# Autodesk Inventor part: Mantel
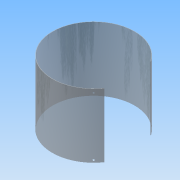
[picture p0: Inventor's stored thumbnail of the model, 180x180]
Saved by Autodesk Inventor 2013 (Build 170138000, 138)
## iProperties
Created: 2012-10
Part Number: Mantel
Material: Glas
Document SubType Name: Blech
Designer: Ente
Density: 2.18 g/cm^3
Mass: 137.687 g
Surface Area: 1275.35 cm^2
Volume: 63.1592 cm^3
Sheet Metal Rule: Standard
Author: Ente
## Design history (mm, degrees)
sketch "Skizze1"
  geometry: L1 (0, -27.3)-(0, 163.8) reference; L2 (-123.9, 0)-(123.9, 0) reference; L3 (88.125, 0)-(87.125, 0); L4 (87.125, 0)-(87.125, 136.5); L5 (87.125, 136.5)-(88.125, 136.5); L6 (88.125, 136.5)-(88.125, 0); 1 further point
  constraints: 8 end point, 2 parallel, 1 horizontal, 1 perpendicular, 1 point on line
  dimensions: "d0" = 1 distance of L4.end L5.end; "d3" = 136.5 distance of L5.end L3.start; "d5" = 174.25 diameter of L4 L1
revolve "Umdrehung1" sketch "Skizze1" stored, may be unused: angle "d4" = 291 deg
workplane "Arbeitsebene4"
  workplane "Arbeitsebene3"
sketch "Skizze3"
  geometry: L1 (0, -98.25)-(0, 96) reference; L2 (-175.221, -68.25)-(175.221, -68.25) reference; 2 further points
  constraints: 1 point on line
  dimensions: "d12" = 5 distance from line of L2 point (0, -63.25)
hole "Bohrung1" sketch "Skizze3" at (0, -63.25) diameter "d13" = 3.4; stored, may be unused: countersink angle "d17" = 90 deg, drill point angle "d19" = 118 deg; dims "d14" = 6, "d15" = 4, "d16" = 2, "d18" = 8
pattern_circular "Runde Anordnung1" dims angle "d21" = 90 deg
workplane "Arbeitsebene7"
  workpoint "Arbeitspunkt1"
mirror "Spiegeln1"
workplane "Arbeitsebene8"
sketch "Skizze5"
  geometry: L1 (88.125, -68.25)-(-88.125, -68.25) reference; L2 (-88.125, -68.25)-(-88.125, 68.25) reference; L3 (88.125, -68.25)-(88.125, 68.25) reference; L4 (88.125, 68.25)-(-88.125, 68.25) reference; L5 (0, 98.7)-(0, -98.7) reference; L6 (-45, -61.75)-(45, -61.75); L7 (45, -61.75)-(45, -1.75); L8 (45, -1.75)-(-45, -1.75); L9 (-45, -1.75)-(-45, -61.75); 4 further points
  constraints: 8 end point, 2 parallel, 1 horizontal, 1 perpendicular, 1 other
  dimensions: "d33" = 90 distance of L6.start L6.end; "d35" = 60 distance of L8.end L6.start; "d36" = 70 distance between parallel lines of L4 L8
extrude "Extrusion1" cut sketch "Skizze5" stored distance "d37" = 10; taper "d39" = 0 deg; dims "d38" = 50, "d40" = 0
sketch "Skizze6" dims "d41" = 177
  geometry: L1 (0, 123.9)-(0, -123.9) reference; L2 (0, 0)-(-22.905, 85.484); 1 further point
  constraints: 2 end point, 1 coincident, 3 other
  dimensions: "d43" = 15 deg angle of L1 L2
workplane "Arbeitsebene9"
node "Volumenkörper1"
workplane "Arbeitsebene2"
workplane "Arbeitsebene6"
other parameters: "d6" = 45 deg, "d11" = 90 deg, "Stärke" = 0.5, "KFaktor" = 4.4, "Biegeradius" = 0.5 (= Stärke), "BreiteBiegungsfreistellung" = 0.5 (= Stärke), "TiefeBiegungsfreistellung" = 0.25 (= 0.5 x Stärke), "GrößeEckenfreistellung" = 2 (= 4 x Stärke), "AbstandVerbindung" = 0.01, "MinimalRest" = 1 (= 2 x Stärke), "Übergangsradius" = 0.5 (= Biegeradius), "JacobiRadiusGröße" = 0.5 (= Stärke), "Abstandsgröße" = 0.5 (= Stärke), "d24" = 108 deg
